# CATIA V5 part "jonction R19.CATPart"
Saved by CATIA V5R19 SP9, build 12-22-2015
Part number: Part1
Bounding box of the stored display mesh (mm): x -1.342 to -1.342, y 12.317 to 12.317, z 120 to 120
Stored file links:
  C:\Users\hbezard\Documents\Perso\imprimante 3d\pieces\rincepot\jonction R19.CATPart
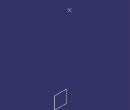
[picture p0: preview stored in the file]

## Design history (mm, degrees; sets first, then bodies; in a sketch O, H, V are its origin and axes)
Parameters
  `dia admi` = 22
  `dia evac` = 10
  `paroies hp` = 2
  `paroies bp` = 2
  `longueur filetee` = 5
  `pas jonction` = 2
  `prof filet jonction` = 1
  `dia gourde` = 12
  `pas gourde` = 2
  `entree gourde` = 8
  `longueur jonction` = 30
  `dia injection` = 8
  `longueur injection` = 110
  `longueur gourde` = 30
  `dia inter injection` = 6
  Real = 0
Body1 (main body)
  Sketch1 on yz-plane, origin (0, 0, 0), H (0, 1, 0), V (0, 0, 1)
    line L1 (0, 5) -> (0, 6)
    line L2 (0, 6) -> (5.5, 6)
    line L3 (5.5, 6) -> (5.5, 8)
    line L4 (5.5, 8) -> (30, 8)
    line L5 (30, 8) -> (30, 7)
    line L6 (30, 7) -> (24.5, 7)
    line L7 (24.5, 7) -> (24.5, 5)
    line L8 (24.5, 5) -> (0, 5)
    reference intersected line E1 through (0, 0) direction (0, 1) from zx-plane
    axis line L9 (-32.3822, 0) -> (183.7177, 0)
    line L10 (0, 11) -> (0, 12)
    line L11 (0, 12) -> (5.5, 12)
    line L12 (5.5, 14) -> (30, 14)
    line L13 (30, 14) -> (30, 13)
    line L14 (30, 13) -> (24.5, 13)
    line L15 (24.5, 11) -> (0, 11)
    line L16 (5.5, 12) -> (5.5, 14)
    line L17 (24.5, 13) -> (24.5, 11)
    point P19 (-31.9622, 57.8884)
    reference intersected line E2 through (0, 0) direction (-1, 0) from xy-plane
    distance L2 L8 = 1
    distance L8 L9 = 5
    angle L2 L3 = 90
    length L2 = 5.5
    distance L1 L5 = 30
    length L6 = 5.5 {= Sketch1.length(L2)}
    distance L4 L6 = 1 {= Sketch1.distance(L2 L8)}
    distance L11 L15 = 1
    angle L11 L16 = 90
    length L11 = 5.5
    distance L10 L13 = 30
    length L14 = 5.5 {= Sketch1.length(L11)}
    distance L12 L14 = 1 {= Sketch1.distance(L11 L15)}
    distance L15 L9 = 11
    distance L14 L11 = 1
    distance L6 L2 = 1
    vertical: L1 V, L5 V, L10 V, L13 V
    horizontal: L2 H, L4 H, L6 H, L8 H, L9 H, L11 H, L12 H, L14 H, L15 H
    coincidence: L1 E1, L10 E1, L9 E2
    parallelism: L7 L3, L17 L16
  Shaft1 "jonction": profile Sketch1, axis Sketch1.L9, angle 360
  Plane1: type Offset, RefPlane xy-plane, Offset 20
  Sketch2 on Plane1, origin (0, 0, 20), H (1, 0, 0), V (0, 1, 0)
    circle A1 centre (0, 15) radius 7.5
    point P1 (0, 15)
    reference intersected line E1 through (0, 0) direction (0, 1) from yz-plane
    reference intersected line E2 through (0, 0) direction (-1, 0) from zx-plane
    distance P1 E2 = 15
    radius A1 = 7.5
    coincidence: P1 E1
  Pad1 "gourde": profile Sketch2, direction (0, 0, -1), up to face of Shaft1 from Sketch1.L12
  Sketch3 on Plane1, origin (0, 0, 20), H (1, 0, 0), V (0, 1, 0)
    point P1 (0, 15)
    reference intersected line E1 through (0, 0) direction (0, 1) from yz-plane
    reference intersected line E2 through (0, 0) direction (-1, 0) from zx-plane
    circle A1 centre (0, 15) radius 3
    distance P1 E2 = 15
    radius A1 = 3
    coincidence: P1 E1
  Pocket1: profile a sketch, direction (0, 0, -1), up to face of Shaft1 from Sketch1.L15
  Pad2: profile Sketch3, direction (0, 0, -1), up to face of Shaft1 from Sketch1.L4, opposite side length 100
  Sketch4 on Plane1, origin (0, 0, 20), H (1, 0, 0), V (0, 1, 0)
    circle A1 centre (0, 15) radius 2
    reference projected point E1 (0, 15) from axis of face of Pad2 from Sketch3.A1
    reference projected circle E2 centre (0, 15) radius 3 from Sketch3.A1
    distance A1 E2 = 1
    concentricity: A1 E1
  Pocket2: profile Sketch4, direction (0, 0, -1), through (limit type 6), opposite side length 98
  Plane2: type Angle, RefPlane yz-plane, Direction Y axis, Angle -30
  Plane3: type Offset, RefPlane {inverselocal InverseElem Plane2}, Offset 10, reversed
  Sketch5 on Plane3, origin (-4.0798, 0, 27.0665), H (0, -1, 0), V (-0.5, 0, 0.866)
    line L1 (-6, -23.9802) -> (-7.3377, -23.9802)
    line L2 (-7.3377, -23.9802) -> (-7.3377, -26.9802)
    line L3 (-7.3377, -26.9802) -> (-6, -26.9802)
    line L4 (-6, -26.9802) -> (-6, -23.9802)
    point P5 (-24, -23.9802)
    line L5 (-24, -23.9802) -> (-22.6623, -23.9802)
    line L6 (-22.6623, -23.9802) -> (-22.6623, -26.9802)
    line L7 (-22.6623, -26.9802) -> (-24, -26.9802)
    line L8 (-24, -26.9802) -> (-24, -23.9802)
    point P7 (-22.6623, -26.9802)
    reference intersected line E1 through (0, 0) direction (0, -1) from face of Shaft1 from Sketch1.L10
    reference intersected line E2 through (-30, 0) direction (0, -1) from face of Shaft1 from Sketch1.L13
    reference projected line E3 through (0, -25.4802) direction (-1, 0) from axis of face of Shaft1 from Sketch1.L8
    length L3 = 1.3377
    length L7 = 1.3377 {= Sketch5.length(L3)}
    distance L3 L1 = 3
    distance L4 E1 = 6
    distance L8 E2 = 6
    horizontal: L1 H, L3 H, L5 H, L7 H
    vertical: L2 V, L4 V, L6 V, L8 V
    coincidence: P5 L1, P7 L3
    symmetry: L3 L1 E3
  Pad3: profile Sketch5, direction (-0.866, 0, -0.5), up to face of Shaft1 from Sketch1.L4, opposite side up to face of Shaft1 from Sketch1.L15
  Mirror1: of Pad3, about yz-plane
  Plane4: type Offset, RefPlane xy-plane, Offset 10, reversed
  Sketch6 on Plane4, origin (0, 0, -10), H (1, 0, 0), V (0, 1, 0)
    point P1 (0, 8)
    line L1 (1, 10) -> (1, 6)
    line L2 (1, 6) -> (-1, 6)
    line L3 (-1, 6) -> (-1, 10)
    line L4 (-1, 10) -> (1, 10)
    point P6 (0, 22)
    line L5 (1, 24) -> (1, 20)
    line L6 (1, 20) -> (-1, 20)
    line L7 (-1, 20) -> (-1, 24)
    line L8 (-1, 24) -> (1, 24)
    point P8 (1, 20)
    reference projected line E1 through (0, 0) direction (0, 1) from axis of face of Shaft1 from Sketch1.L8
    reference intersected line E2 through (0, 0) direction (-1, 0) from face of Shaft1 from Sketch1.L10
    reference projected line E3 (-13, 30) -> (13, 30) from edge [face of Shaft1 from Sketch1.L12 | face of Shaft1 from Sketch1.L13]
    length L3 = 4
    length L7 = 4 {= Sketch6.length(L3)}
    length L4 = 2
    distance L2 E2 = 6
    distance L8 E3 = 6
    vertical: L1 V, L3 V, L5 V, L7 V
    horizontal: L2 H, L4 H, L6 H, L8 H
    equidistance: L1 L3 P1, L2 L4 P1, L5 L7 P6, L6 L8 P6
    coincidence: P8 L1, P1 E1, L7 L3
  Pad4: profile Sketch6, direction (0, 0, 1), up to face of Shaft1 from Sketch1.L4, opposite side up to face of Shaft1 from Sketch1.L15
  Fillet1: radius 0.5, on face of Pad4 from Sketch6.L2; face of Pad4 from Sketch6.L1; face of Pad4 from Sketch6.L3; face of Pad4 from Sketch6.L4; face of Pad4 from Sketch6.L8; face of Pad4 from Sketch6.L5; face of Pad4 from Sketch6.L6; face of Pad4 from Sketch6.L7
  Fillet2: radius 0.5, on face of Pad3 from Sketch5.L8; face of Pad3 from Sketch5.L7; face of Pad3 from Sketch5.L5; face of Pad3 from Sketch5.L6; face of Pad3 from Sketch5.L4; face of Pad3 from Sketch5.L3; face of Pad3 from Sketch5.L1; face of Pad3 from Sketch5.L2; face of Mirror1 (x8)
  Fillet3: radius 0.5, on edge [face of Shaft1 from Sketch1.L4 | face of Pad2 from Sketch3.A1]
  Fillet4: radius 0.5, on edge [face of Pad1 from Sketch2.A1 | face of Shaft1 from Sketch1.L12]
  Point1: type Center, Curve edge [face of Shaft1 from Sketch1.L13 | face of Shaft1 from Sketch1.L14]
  Helix1: Direction Y axis, RefPoint {point type Coord, X 0, Y -1.155, Z 0, RefPoint vertex [element of Sketch1 | element of Sketch1]}, Pitch 2, Height 3.5, TaperAngle 0
  Sketch7 on yz-plane, origin (0, 0, 0), H (0, 1, 0), V (0, 0, 1)
    point P1 (3.7679, 12)
    line L1 (3.7679, 12) -> (4.9226, 12)
    point P2 (4.9226, 12)
    line L2 (4.9226, 12) -> (4.3453, 13)
    point P3 (4.3453, 13)
    line L3 (4.3453, 13) -> (3.7679, 12)
    axis line L4 (4.3453, 15.5745) -> (4.3453, 9.1301)
    reference projected line E1 (5.5, 12) -> (0, 12) from Sketch1.L11
    reference projected line E2 (5.5, 14) -> (5.5, -14) from edge [face of Shaft1 from Sketch1.L16 | face of Shaft1 from Sketch1.L12]
    length L4 = 6.4444
    angle L2 L1 = 60
    distance L1 P3 = 1
    distance L1 E1 = 0
    distance L4 E2 = 1.1547 {= Sketch7.length(L1)}
    length L1 = 1.1547 (reference)
    horizontal: L1 H
    vertical: L4 V
    symmetry: P2 P1 L4
    coincidence: P3 L4
  Rib1: profile Sketch7, centre curve Helix1
  Fillet5: radius 0.5, on face of Rib1, deactivated
  Fillet6: radius 0.5, on face of Rib1
  Helix2: Direction Y axis, RefPoint vertex [element of Sketch1 | element of Sketch1], Pitch 2, Height 4, TaperAngle 0
  Sketch8 on yz-plane, origin (0, 0, 0), H (0, 1, 0), V (0, 0, 1)
    point P1 (0, 6)
    line L1 (0, 6) -> (1.1547, 6)
    point P2 (1.1547, 6)
    line L2 (1.1547, 6) -> (0.5774, 7)
    point P3 (0.5774, 7)
    line L3 (0.5774, 7) -> (0, 6)
    axis line L4 (0.5774, 18.6338) -> (0.5774, 12.1894)
    reference projected point E1 (0, 6) from vertex [element of Sketch1 | element of Sketch1]
    length L4 = 6.4444
    angle L2 L1 = 60
    distance L1 P3 = 1
    horizontal: L1 H
    vertical: L4 V
    symmetry: P2 P1 L4
    coincidence: P3 L4, P1 E1
  Rib2: profile Sketch8, centre curve Helix2
  Fillet7: radius 0.5, on face of Rib2
  Fillet8: radius 0.5, on face of Rib2
  Sketch9 on yz-plane, origin (0, 0, 0), H (0, 1, 0), V (0, 0, 1)
    point P1 (30, 13)
    line L1 (30, 13) -> (28.8453, 13)
    point P2 (28.8453, 13)
    line L2 (28.8453, 13) -> (29.4226, 12)
    point P3 (29.4226, 12)
    line L3 (29.4226, 12) -> (30, 13)
    axis line L4 (29.4226, 19.8788) -> (29.4226, 13.4344)
    reference projected point E1 (30, 13) from vertex [element of Sketch1 | element of Sketch1]
    length L4 = 6.4444
    angle L2 L1 = 60
    distance L1 P3 = 1
    horizontal: L1 H
    vertical: L4 V
    symmetry: P2 P1 L4
    coincidence: P3 L4, P1 E1
  Sketch10 on yz-plane, origin (0, 0, 0), H (0, 1, 0), V (0, 0, 1)
    point P1 (30, 7)
    line L1 (30, 7) -> (28.8453, 7)
    point P2 (28.8453, 7)
    line L2 (28.8453, 7) -> (29.4226, 6)
    point P3 (29.4226, 6)
    line L3 (29.4226, 6) -> (30, 7)
    axis line L4 (29.4226, 13.8788) -> (29.4226, 7.4344)
    reference projected point E1 (30, 7) from vertex [element of Sketch1 | element of Sketch1]
    length L4 = 6.4444
    angle L2 L1 = 60
    distance L1 P3 = 1
    horizontal: L1 H
    vertical: L4 V
    symmetry: P2 P1 L4
    coincidence: P3 L4, P1 E1
  Helix3: Direction Y axis, RefPoint vertex [element of Sketch1 | element of Sketch1], Pitch 2, Height 4, TaperAngle 0
  Helix4: Direction Y axis, RefPoint vertex [element of Sketch1 | element of Sketch1], Pitch 2, Height 4, TaperAngle 0
  Rib3: profile Sketch9, centre curve Helix3
  Rib4: profile Sketch10, centre curve Helix4
  Fillet9: radius 0.5, on face of Rib3
  Fillet10: radius 0.5, on face of Rib4
  Fillet11: radius 0.5, on face of Rib4
  Fillet12: radius 0.5, on face of Rib3
  Sketch11 on start face of Pad2, origin (0, 15, 120), H (1, 0, 0), V (0, 1, 0)
    point P1 (0, 0)
  Hole1: placed by Sketch11, at (0, 15, 120) direction (0, 0, -1), diameter 1, through (limit type 6)
  Point2: type OnCurve, Support edge [face of Pad2 from Sketch3.A1 | start face of Pad2], RefPoint {extremum Reference edge [face of Pad2 from Sketch3.A1 | start face of Pad2], Direction (1, 2, 3)}, Ratio 0.5
  Helix5: Direction {line type PtDir, RefPoint {point type Center, Curve edge [face of Pad2 from Sketch3.A1 | start face of Pad2]}, Direction start face of Pad2, Start 0, End 20}, RefPoint {point type OnCurve, Support a sketch, RefPoint {extremum Reference a sketch, Direction (1, 2, 3)}, Ratio 0.5}, Pitch 2, Height 5, TaperAngle 0
  Sketch12 on yz-plane, origin (0, -0.7113, -0.4445), H (0, 1, 0), V (0, 0, 1)
    point P1 (15.7113, 116.4445)
    reference projected line E1 through (15.7113, 0) direction (0, 1) from axis of face of Pad2 from Sketch3.A1
    reference intersected line E2 (12.7113, 120.4445) -> (18.7113, 120.4445) from start face of Pad2
    distance P1 E2 = 4
    coincidence: P1 E1
  Hole2: placed by Sketch12, at (0, 15, 116) direction (-1, 0, 0), diameter 1, through (limit type 3)
  CircPattern1: of Hole2, instances 8, angular step 45, axis from {line type PtDir, RefPoint {point type Center, Curve edge [face of Pad2 from Sketch3.A1 | start face of Pad2]}, Direction start face of Pad2, Start 0, End 20}
  RectPattern1: of CircPattern1, direction 1 instances 10, spacing 9, along Z axis reversed
  Plane5: type Normal, Curve edge [start face of Pad1 | face of Pocket1], RefPoint vertex of Helix5
  Sketch13 on Plane5, origin (-6.7082, 1.5836, 0), H (0.4472, 0.8944, 0), V (0, 0, 1)
    point P1 (8.5, 20)
    line L1 (8.5, 20) -> (8.5, 18.8453)
    point P2 (8.5, 18.8453)
    line L2 (8.5, 18.8453) -> (9.5, 19.4226)
    point P3 (9.5, 19.4226)
    line L3 (9.5, 19.4226) -> (8.5, 20)
    axis line L4 (6.1394, 19.4226) -> (12.5838, 19.4226)
    point P4 (6.1394, 19.4226)
    reference projected point E1 (8.5, 20) from vertex of Helix5
    length L4 = 6.4444
    angle L2 L1 = 60
    distance L1 P3 = 1
    distance L1 P4 = 2.3606
    symmetry: P2 P1 L4
    coincidence: P3 L4, P1 E1
    perpendicularity: L4 L1
    vertical: L1 V
  Rib5: profile Sketch13, centre curve Helix5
